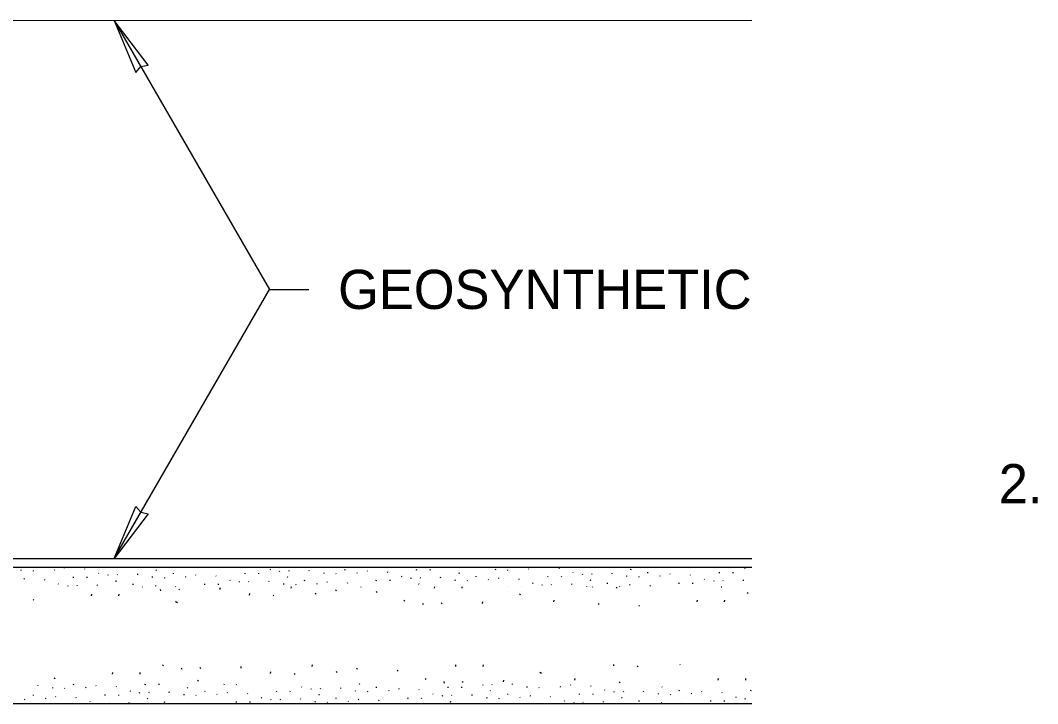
# Model space of a CAD drawing. Extents: x 99862 to 103151, y 100000 to 111076.
# Drawn here: x 100425.5 to 100840.9, y 110543.7 to 110822.9 of the extents above; entities that cross this region are included whole.
import ezdxf

# ---------------------------------------------------------------- set-up
doc = ezdxf.new("R2010")
doc.units = 0
for name, color, linetype in [('Level 11', 7, 'Continuous'), ('Level 15', 7, 'Continuous'), ('Level 18', 7, 'Continuous'), ('Level 20', 7, 'Continuous'), ('Level 24', 7, 'Continuous')]:
    doc.layers.add(name, color=color, linetype=linetype)

msp = doc.modelspace()

# ---------------------------------------------------------------- linework, layer by layer
at = {"layer": 'Level 11'}
msp.add_line((100165.98, 110599.43), (100724.21, 110599.43), dxfattribs=at)
at = {"layer": 'Level 15'}
for p, q in [((100463.8, 110822.89), (100527.26, 110712.97)), ((100463.8, 110603.05), (100527.26, 110712.97)), ((100527.26, 110712.97), (100543.26, 110712.97))]:
    msp.add_line(p, q, dxfattribs=at)
for points in [[(100463.8, 110822.89), (100472.63, 110801.62), (100474.69, 110804.03), (100477.8, 110804.61)], [(100463.8, 110603.05), (100472.63, 110624.31), (100474.69, 110621.9), (100477.8, 110621.33)]]:
    msp.add_lwpolyline(points, close=True, dxfattribs=at)
at = {"layer": 'Level 18'}
for p, q in [((100425.9, 110598.1), (100425.95, 110598.44)), ((100430.68, 110598.1), (100430.87, 110597.93)), ((100439.29, 110598.48), (100439.48, 110598.32)), ((100443.44, 110599.2), (100443.64, 110599.03)), ((100451.73, 110598.81), (100451.92, 110598.64)), ((100480.84, 110598.37), (100481.03, 110598.2)), ((100481, 110598.32), (100481.19, 110598.15)), ((100527.46, 110598.66), (100527.65, 110598.49)), ((100531.26, 110598.04), (100531.38, 110597.74)), ((100535.07, 110598.08), (100535.26, 110597.92)), ((100543.5, 110597.98), (100543.55, 110598.32)), ((100558.05, 110598.3), (100558.1, 110598.65)), ((100567.08, 110597.97), (100567.27, 110597.8)), ((100587.32, 110598.31), (100587.37, 110598.66)), ((100592.91, 110598.3), (100592.96, 110598.65)), ((100601.38, 110599.43), (100601.42, 110599.33)), ((100619.57, 110598.46), (100619.62, 110598.8)), ((100624.35, 110598.46), (100624.54, 110598.29)), ((100632.96, 110598.84), (100633.15, 110598.68)), ((100637.27, 110599.43), (100637.31, 110599.39)), ((100645.4, 110599.17), (100645.6, 110599)), ((100674.51, 110598.73), (100674.7, 110598.56)), ((100674.67, 110598.68), (100674.86, 110598.51)), ((100721.13, 110599.02), (100721.32, 110598.85)), ((100427.01, 110594.8), (100427.2, 110594.63)), ((100435.3, 110594.4), (100435.49, 110594.24)), ((100447.25, 110595.14), (100447.3, 110595.48)), ((100452.84, 110595.13), (100452.89, 110595.47)), ((100457.42, 110597.07), (100457.61, 110596.9)), ((100461.23, 110596.45), (100461.34, 110596.15)), ((100464.4, 110593.96), (100464.6, 110593.79)), ((100464.56, 110593.92), (100464.76, 110593.75)), ((100465.03, 110596.5), (100465.23, 110596.33)), ((100473.46, 110596.39), (100473.52, 110596.73)), ((100479.5, 110595.28), (100479.55, 110595.62)), ((100484.28, 110595.29), (100484.47, 110595.12)), ((100488.01, 110596.72), (100488.07, 110597.06)), ((100492.89, 110595.67), (100493.08, 110595.5)), ((100497.04, 110596.38), (100497.24, 110596.21)), ((100505.33, 110595.99), (100505.52, 110595.82)), ((100511.02, 110594.25), (100511.21, 110594.08)), ((100514.83, 110593.64), (100514.94, 110593.34)), ((100517.28, 110596.73), (100517.34, 110597.07)), ((100518.63, 110593.68), (100518.83, 110593.51)), ((100522.87, 110596.72), (100522.93, 110597.06)), ((100527.06, 110593.57), (100527.12, 110593.92)), ((100534.44, 110595.55), (100534.63, 110595.38)), ((100534.6, 110595.51), (100534.79, 110595.34)), ((100541.61, 110593.9), (100541.67, 110594.24)), ((100549.53, 110596.87), (100549.59, 110597.21)), ((100550.64, 110593.57), (100550.84, 110593.4)), ((100554.31, 110596.87), (100554.51, 110596.7)), ((100562.92, 110597.26), (100563.12, 110597.09)), ((100570.88, 110593.91), (100570.94, 110594.26)), ((100575.37, 110597.58), (100575.56, 110597.41)), ((100576.47, 110593.9), (100576.53, 110594.25)), ((100581.06, 110595.84), (100581.25, 110595.67)), ((100584.86, 110595.22), (100584.98, 110594.92)), ((100588.67, 110595.27), (100588.86, 110595.1)), ((100597.1, 110595.16), (100597.15, 110595.51)), ((100603.13, 110594.05), (100603.19, 110594.4)), ((100604.48, 110597.14), (100604.67, 110596.97)), ((100604.63, 110597.1), (100604.83, 110596.93)), ((100607.91, 110594.06), (100608.11, 110593.89)), ((100611.65, 110595.49), (100611.7, 110595.83)), ((100616.52, 110594.44), (100616.72, 110594.27)), ((100620.68, 110595.16), (100620.87, 110594.99)), ((100628.97, 110594.77), (100629.16, 110594.6)), ((100640.92, 110595.5), (100640.97, 110595.84)), ((100646.51, 110595.49), (100646.56, 110595.83)), ((100651.09, 110597.43), (100651.29, 110597.26)), ((100654.9, 110596.81), (100655.02, 110596.51)), ((100658.08, 110594.32), (100658.27, 110594.15)), ((100658.23, 110594.28), (100658.43, 110594.11)), ((100658.7, 110596.86), (100658.9, 110596.69)), ((100667.13, 110596.75), (100667.19, 110597.09)), ((100673.17, 110595.64), (100673.22, 110595.99)), ((100677.95, 110595.65), (100678.14, 110595.48)), ((100681.68, 110597.08), (100681.74, 110597.42)), ((100686.56, 110596.03), (100686.75, 110595.86)), ((100690.71, 110596.74), (100690.91, 110596.57)), ((100699, 110596.35), (100699.2, 110596.18)), ((100704.69, 110594.61), (100704.89, 110594.44)), ((100708.5, 110594), (100708.62, 110593.7)), ((100710.95, 110597.09), (100711.01, 110597.43)), ((100712.3, 110594.04), (100712.5, 110593.87)), ((100716.55, 110597.08), (100716.6, 110597.42)), ((100720.73, 110593.93), (100720.79, 110594.28)), ((100440.99, 110592.66), (100441.18, 110592.5)), ((100444.79, 110592.05), (100444.91, 110591.75)), ((100448.6, 110592.09), (100448.79, 110591.92)), ((100457.03, 110591.98), (100457.08, 110592.33)), ((100471.58, 110592.31), (100471.63, 110592.66)), ((100475.24, 110591.43), (100475.37, 110591.31)), ((100480.61, 110591.98), (100480.8, 110591.81)), ((100482.59, 110590.42), (100482.83, 110589.82)), ((100488.9, 110591.59), (100489.08, 110591.43)), ((100490.2, 110590.51), (100490.59, 110590.17)), ((100500.85, 110592.32), (100500.9, 110592.67)), ((100506.44, 110592.31), (100506.49, 110592.66)), ((100507.06, 110590.29), (100507.17, 110590.98)), ((100533.1, 110592.46), (100533.15, 110592.81)), ((100536.16, 110590.94), (100536.24, 110591.43)), ((100537.88, 110592.47), (100538.07, 110592.3)), ((100546.49, 110592.85), (100546.68, 110592.68)), ((100554.23, 110590.28), (100554.61, 110589.94)), ((100558.93, 110593.18), (100559.12, 110593.01)), ((100564.62, 110591.44), (100564.63, 110591.43)), ((100570.8, 110589.5), (100571.19, 110589.16)), ((100588.04, 110592.73), (100588.23, 110592.56)), ((100588.2, 110592.69), (100588.39, 110592.52)), ((100594.7, 110590.97), (100594.78, 110591.43)), ((100595.27, 110591.43), (100595.27, 110591.43)), ((100605.89, 110590.95), (100605.96, 110591.43)), ((100624.54, 110591.43), (100624.54, 110591.44)), ((100630.13, 110591.43), (100630.13, 110591.43)), ((100634.66, 110593.02), (100634.85, 110592.86)), ((100638.46, 110592.41), (100638.58, 110592.11)), ((100642.27, 110592.45), (100642.46, 110592.28)), ((100650.7, 110592.34), (100650.75, 110592.69)), ((100656.76, 110591.43), (100656.79, 110591.58)), ((100659.2, 110591.25), (100659.23, 110591.43)), ((100665.25, 110592.67), (100665.3, 110593.02)), ((100668.77, 110591.26), (100669.15, 110590.92)), ((100670.13, 110591.62), (100670.32, 110591.46)), ((100674.28, 110592.34), (100674.47, 110592.17)), ((100682.57, 110591.95), (100682.76, 110591.78)), ((100694.52, 110592.68), (100694.57, 110593.03)), ((100700.11, 110592.67), (100700.16, 110593.02)), ((100711.68, 110591.51), (100711.77, 110591.43)), ((100711.83, 110591.46), (100711.88, 110591.43)), ((100430.73, 110586.32), (100431.12, 110585.99)), ((100454.63, 110587.79), (100454.74, 110588.48)), ((100465.82, 110587.77), (100465.93, 110588.46)), ((100488.95, 110585.44), (100489.33, 110585.1)), ((100489.26, 110585.35), (100489.65, 110585.02)), ((100519.13, 110588.07), (100519.24, 110588.76)), ((100528.7, 110588.08), (100529.08, 110587.75)), ((100545.92, 110588.85), (100546.3, 110588.51)), ((100582.18, 110586.02), (100582.57, 110585.68)), ((100614.26, 110584.66), (100614.37, 110585.35)), ((100629.33, 110588.53), (100629.72, 110588.19)), ((100643.36, 110585.31), (100643.47, 110586)), ((100701.9, 110585.33), (100702.01, 110586.02)), ((100713.09, 110585.31), (100713.2, 110586.01)), ((100722.25, 110589.2), (100722.64, 110588.86)), ((100589.79, 110584.79), (100590.03, 110584.19)), ((100597.4, 110584.88), (100597.79, 110584.54)), ((100661.43, 110584.65), (100661.81, 110584.31)), ((100678, 110583.87), (100678.39, 110583.53)), ((100463.22, 110555.73), (100463.33, 110556.43)), ((100474.41, 110555.72), (100474.51, 110556.41)), ((100483.57, 110559.6), (100483.96, 110559.26)), ((100491.18, 110558.36), (100491.42, 110557.76)), ((100498.79, 110558.45), (100499.18, 110558.11)), ((100515.65, 110558.24), (100515.76, 110558.93)), ((100527.72, 110556.02), (100527.83, 110556.71)), ((100544.75, 110558.89), (100544.86, 110559.58)), ((100554.51, 110556.8), (100554.89, 110556.46)), ((100562.81, 110558.23), (100563.2, 110557.89)), ((100579.39, 110557.45), (100579.78, 110557.11)), ((100603.29, 110558.91), (100603.4, 110559.6)), ((100614.48, 110558.89), (100614.58, 110559.58)), ((100637.61, 110556.56), (100637.99, 110556.22)), ((100637.92, 110556.48), (100638.31, 110556.14)), ((100667.79, 110559.19), (100667.88, 110559.78)), ((100677.36, 110559.21), (100677.74, 110558.87)), ((100694.79, 110559.78), (100694.96, 110559.63)), ((100439.32, 110554.27), (100439.71, 110553.93)), ((100497.85, 110553.3), (100498.24, 110552.96)), ((100537.28, 110556.03), (100537.67, 110555.69)), ((100590.77, 110553.97), (100591.16, 110553.63)), ((100598.38, 110552.73), (100598.62, 110552.13)), ((100605.99, 110552.82), (100606.38, 110552.48)), ((100622.85, 110552.61), (100622.96, 110553.3)), ((100651.95, 110553.26), (100652.06, 110553.95)), ((100670.01, 110552.6), (100670.4, 110552.26)), ((100710.49, 110553.28), (100710.6, 110553.97)), ((100721.68, 110553.26), (100721.79, 110553.95)), ((100432.75, 110551.12), (100432.8, 110551.47)), ((100438.78, 110550.01), (100438.83, 110550.36)), ((100443.56, 110550.02), (100443.75, 110549.85)), ((100447.3, 110551.45), (100447.34, 110551.75)), ((100452.17, 110550.4), (100452.37, 110550.23)), ((100456.33, 110551.12), (100456.52, 110550.95)), ((100464.62, 110550.73), (100464.81, 110550.56)), ((100470.31, 110548.99), (100470.5, 110548.82)), ((100474.11, 110548.37), (100474.23, 110548.07)), ((100476.57, 110551.46), (100476.61, 110551.75)), ((100477.92, 110548.41), (100478.11, 110548.25)), ((100482.16, 110551.45), (100482.21, 110551.75)), ((100486.35, 110548.31), (100486.4, 110548.65)), ((100493.72, 110550.28), (100493.92, 110550.11)), ((100500.9, 110548.63), (100500.95, 110548.98)), ((100508.82, 110551.6), (100508.84, 110551.76)), ((100509.93, 110548.3), (100510.12, 110548.13)), ((100513.6, 110551.61), (100513.79, 110551.44)), ((100518.22, 110547.91), (100518.41, 110547.74)), ((100530.17, 110548.64), (100530.22, 110548.99)), ((100535.76, 110548.63), (100535.81, 110548.98)), ((100540.34, 110550.57), (100540.53, 110550.41)), ((100544.15, 110549.96), (100544.26, 110549.66)), ((100547.95, 110550), (100548.14, 110549.83)), ((100556.38, 110549.89), (100556.44, 110550.24)), ((100562.42, 110548.79), (100562.47, 110549.13)), ((100563.88, 110551.76), (100563.95, 110551.7)), ((100563.99, 110551.76), (100564.11, 110551.66)), ((100567.2, 110548.79), (100567.39, 110548.62)), ((100570.93, 110550.22), (100570.99, 110550.57)), ((100575.81, 110549.17), (100576, 110549.01)), ((100579.96, 110549.89), (100580.15, 110549.72)), ((100588.25, 110549.5), (100588.44, 110549.33)), ((100593.94, 110547.76), (100594.13, 110547.59)), ((100600.2, 110550.23), (100600.26, 110550.58)), ((100605.79, 110550.22), (100605.85, 110550.57)), ((100614.18, 110551.55), (100614.3, 110551.25)), ((100617.36, 110549.06), (100617.55, 110548.89)), ((100617.99, 110551.59), (100618.18, 110551.42)), ((100626.42, 110551.48), (100626.46, 110551.77)), ((100632.45, 110550.37), (100632.51, 110550.72)), ((100637.23, 110550.38), (100637.43, 110550.21)), ((100645.84, 110550.76), (100646.04, 110550.59)), ((100650, 110551.48), (100650.19, 110551.31)), ((100653.8, 110547.42), (100653.86, 110547.76)), ((100658.29, 110551.09), (100658.48, 110550.92)), ((100663.98, 110549.35), (100664.17, 110549.18)), ((100667.78, 110548.73), (100667.9, 110548.43)), ((100671.59, 110548.77), (100671.78, 110548.61)), ((100680.02, 110548.67), (100680.07, 110549.01)), ((100686.05, 110547.56), (100686.11, 110547.9)), ((100686.59, 110551.81), (100686.63, 110551.78)), ((100687.39, 110550.64), (100687.59, 110550.47)), ((100694.57, 110548.99), (100694.62, 110549.34)), ((100699.44, 110547.95), (100699.64, 110547.78)), ((100703.6, 110548.66), (100703.79, 110548.49)), ((100711.89, 110548.27), (100712.08, 110548.1)), ((100723.84, 110549), (100723.89, 110549.35)), ((100427.13, 110545.62), (100427.32, 110545.45)), ((100430.86, 110547.05), (100430.91, 110547.39)), ((100435.74, 110546), (100435.93, 110545.83)), ((100439.89, 110546.71), (100440.08, 110546.54)), ((100448.18, 110546.32), (100448.37, 110546.15)), ((100453.87, 110544.58), (100454.06, 110544.41)), ((100457.68, 110543.97), (100457.76, 110543.75)), ((100460.13, 110547.06), (100460.19, 110547.4)), ((100461.48, 110544.01), (100461.67, 110543.84)), ((100465.72, 110547.05), (100465.78, 110547.39)), ((100469.91, 110543.9), (100469.97, 110544.25)), ((100477.29, 110545.88), (100477.48, 110545.71)), ((100477.45, 110545.84), (100477.64, 110545.67)), ((100484.46, 110544.23), (100484.51, 110544.58)), ((100492.38, 110547.2), (100492.43, 110547.54)), ((100493.49, 110543.9), (100493.66, 110543.75)), ((100497.16, 110547.2), (100497.36, 110547.03)), ((100505.77, 110547.59), (100505.97, 110547.42)), ((100513.73, 110544.24), (100513.79, 110544.59)), ((100519.32, 110544.23), (100519.38, 110544.58)), ((100523.91, 110546.17), (100524.1, 110546)), ((100527.71, 110545.55), (100527.83, 110545.25)), ((100531.52, 110545.6), (100531.71, 110545.43)), ((100539.95, 110545.49), (100540, 110545.84)), ((100545.98, 110544.38), (100546.04, 110544.73)), ((100547.32, 110547.47), (100547.52, 110547.3)), ((100547.48, 110547.43), (100547.67, 110547.26)), ((100550.76, 110544.39), (100550.96, 110544.22)), ((100554.5, 110545.82), (100554.55, 110546.16)), ((100559.37, 110544.77), (100559.57, 110544.6)), ((100563.53, 110545.49), (100563.72, 110545.32)), ((100571.82, 110545.1), (100572.01, 110544.93)), ((100583.77, 110545.83), (100583.82, 110546.17)), ((100589.36, 110545.82), (100589.41, 110546.16)), ((100597.75, 110547.14), (100597.86, 110546.84)), ((100600.92, 110544.65), (100601.12, 110544.48)), ((100601.08, 110544.61), (100601.27, 110544.44)), ((100601.55, 110547.19), (100601.74, 110547.02)), ((100609.98, 110547.08), (100610.04, 110547.42)), ((100616.02, 110545.97), (100616.07, 110546.32)), ((100620.8, 110545.98), (100620.99, 110545.81)), ((100624.53, 110547.41), (100624.59, 110547.75)), ((100629.41, 110546.36), (100629.6, 110546.19)), ((100633.56, 110547.07), (100633.76, 110546.91)), ((100641.85, 110546.68), (100642.04, 110546.51)), ((100647.54, 110544.94), (100647.73, 110544.77)), ((100651.35, 110544.33), (100651.46, 110544.03)), ((100655.15, 110544.37), (100655.35, 110544.2)), ((100659.39, 110547.41), (100659.45, 110547.75)), ((100663.58, 110544.26), (100663.64, 110544.61)), ((100670.96, 110546.24), (100671.15, 110546.07)), ((100671.12, 110546.2), (100671.31, 110546.03)), ((100678.13, 110544.59), (100678.19, 110544.94)), ((100687.16, 110544.26), (100687.36, 110544.09)), ((100690.83, 110547.56), (100691.03, 110547.39)), ((100695.45, 110543.87), (100695.55, 110543.78)), ((100707.4, 110544.6), (100707.46, 110544.95)), ((100712.99, 110544.59), (100713.05, 110544.94)), ((100717.58, 110546.53), (100717.77, 110546.36)), ((100721.38, 110545.91), (100721.5, 110545.62))]:
    msp.add_line(p, q, dxfattribs=at)
at = {"layer": 'Level 24'}
for p, q in [((100168.04, 110822.82), (100724.21, 110822.9)), ((100174.51, 110603.05), (100724.21, 110603.05)), ((100168.04, 110543.71), (100724.21, 110543.78))]:
    msp.add_line(p, q, dxfattribs=at)

# ---------------------------------------------------------------- texts
at = {"layer": 'Level 20'}
for s, p in [('GEOSYNTHETIC', (100555.27, 110704.97)), ('2.', (100824.99, 110625.6))]:
    msp.add_text(s, height=16, dxfattribs=at).set_placement(p)

doc.saveas('drawing.dxf')
